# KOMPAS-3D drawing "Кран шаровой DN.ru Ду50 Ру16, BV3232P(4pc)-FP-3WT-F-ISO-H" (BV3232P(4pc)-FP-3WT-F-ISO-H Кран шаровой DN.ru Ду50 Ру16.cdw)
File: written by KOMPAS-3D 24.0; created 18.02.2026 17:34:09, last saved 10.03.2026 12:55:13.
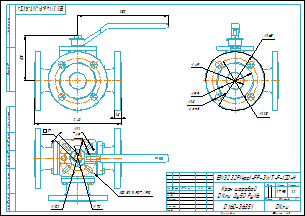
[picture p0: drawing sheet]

Document properties: Автор: R2D2; Форматы листов документа: A3; Полное имя файла: BV3232P(4pc)-FP-3WT-F-ISO-H Кран шаровой DN.ru Ду50 Ру16.m3d; Масса: 17.95; Наименование: Кран шаровой DN.ru Ду50 Ру16; Количество листов документа: 1; Примечание: D160-36351

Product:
- Part/product: Кран шаровой DN.ru Ду50 Ру16  | designation BV3232P(4pc)-FP-3WT-F-ISO-H
    Масса: 17.95
    Раздел спецификации: Прочие изделия
    Примечание: D160-36351

Views: Вид 1, Спереди, Проекционный вид 2
Referenced files in E:\Работа\Зайцев\BV3232P(4pc)-FP-3WL-F-ISO-H Кран шаровой DN.ru Ду15-100 Ру16\DN50\: BV3232P(4pc)-FP-3WL-F-ISO-H Кран шаровой DN.ru Ду50 Ру16.m3d
Referenced files in E:\Работа\Зайцев\BV3232P(4pc)-FP-3WT-F-ISO-H Кран шаровой DN.ru Ду15-100 Ру16\DN50\: BV3232P(4pc)-FP-3WT-F-ISO-H Кран шаровой DN.ru Ду50 Ру16.m3d
Referenced files in E:\Работа\Зайцев\Для компаса\: чертеж DN.ru А3.cdt
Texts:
  BV3232P(4pc)-FP-3WT-F-ISO-H
  чертеж DN.ru А3.cdt
  Кран шаровой
  DN.ru Ду50 Ру16
  Кран шаровой DN.ru Ду50 Ру16
  BV3232P(4pc)-FP-3WT-F-ISO-H Кран шаровой DN.ru Ду50 Ру16
Dimensions and other numbers on the sheet: 0; 3; 2; 4; 240; 18; 125; 250; 165; 99; 49; 4 отв.; 1:2; 1; 17,95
